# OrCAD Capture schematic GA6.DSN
size A
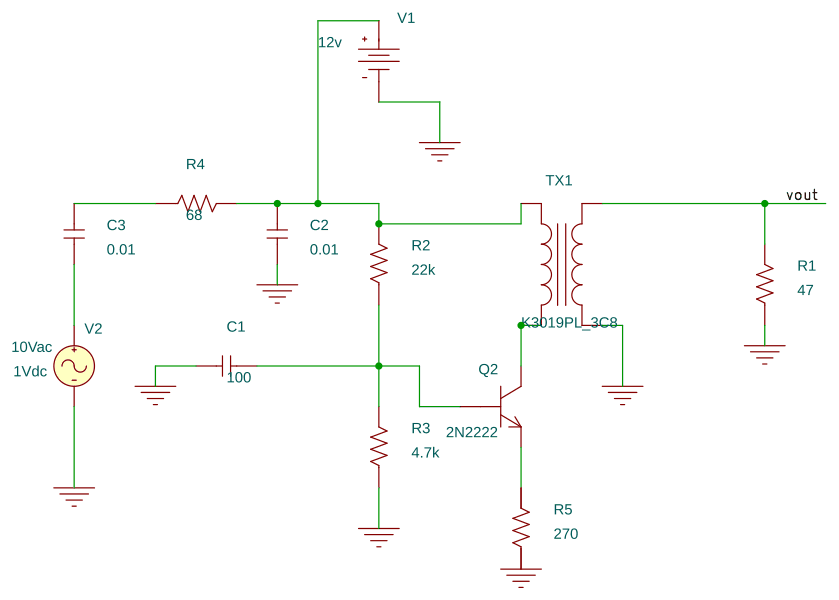
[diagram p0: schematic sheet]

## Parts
C1  100  [RAD/CK05]
C2  0.01  [RAD/CK05]
C3  0.01  [RAD/CK05]
Q2  2N2222  [TO18]
R1  47  [AX/RC05]
R2  22k  [AX/RC05]
R3  4.7k  [AX/RC05]
R4  68  [AX/RC05]
R5  270  [AX/RC05]
TX1  K3019PL_3C8
V1  VDC
V2  VAC

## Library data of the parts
C1-C3 = C
Q2 = 2N2222
R1-R5 = R
TX1 = K3019PL_3C8: COUPLING: 0.5; L1_TURNS: 12; L2_TURNS: 3
V1 = VDC: DC: 12v
V2 = VAC: ACMAG: 10Vac; DC: 1Vdc

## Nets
0: C1.1 C2.1 R1.1 R3.1 R5.1 TX1.4 V1.1(-) V2.2(-)
vout: R1.2 TX1.3
N00207: C2.2 R2.2 R4.2 TX1.1 V1.0(+)
N00239: C1.2 Q2.2(B) R2.1 R3.2
N00408: C3.2 R4.1
N00423: C3.1 V2.1(+)
N00686: Q2.1(E) R5.2
N00799: Q2.3(C) TX1.2
